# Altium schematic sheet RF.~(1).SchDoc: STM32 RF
size A4; Date: Not used; ApprovedBy: Not used; CheckedBy: Not used; Author: Not used; CompanyName: STMicroelectronics; DrawnBy: Not used; Engineer: Not used; Organization: Not used; Address1: Not used; Address2: Not used; Address3: Not used; Address4: Not used; DocumentNumber: Not used; Revision: Not used; SheetNumber: 5; SheetTotal: 5
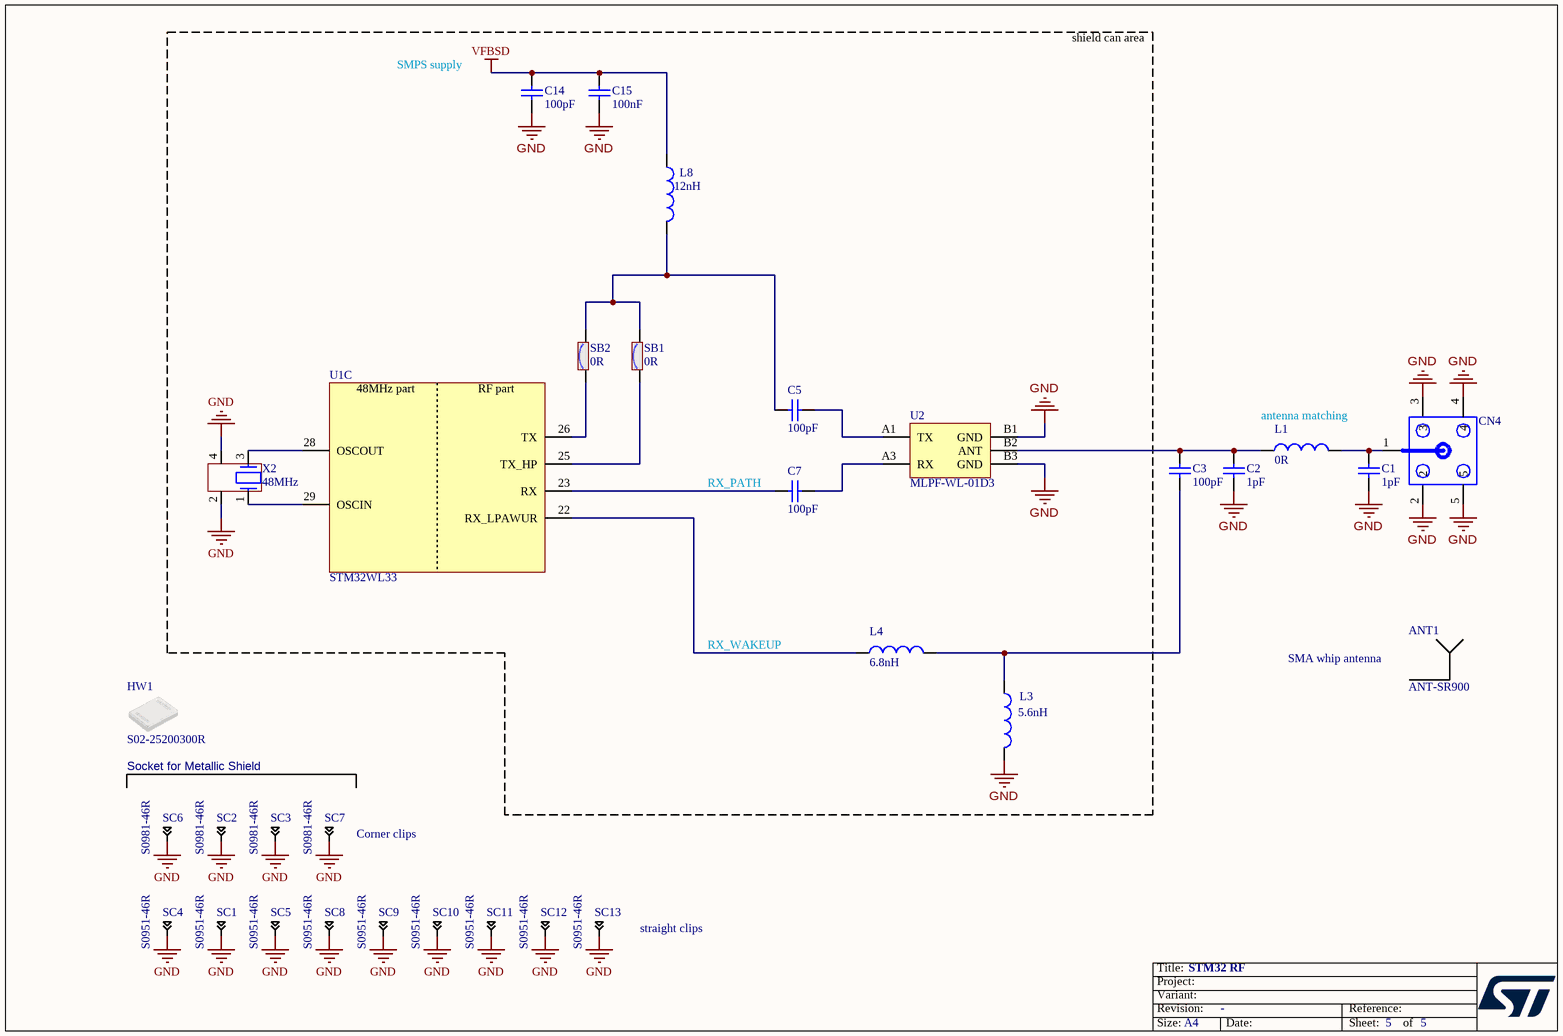
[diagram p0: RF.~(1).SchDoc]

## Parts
ANT1  value ANT-SR900  (hidden comment: ANT)  (mechanical)
C1  value 1pF  [C0402]  (hidden comment: Capacitor)
C2  value 1pF  [C0402]  (hidden comment: Capacitor)
C3  value 100pF  [C0402]  (hidden comment: Capacitor)
C5  value 100pF  [C0402]  (hidden comment: Capacitor)
C7  value 100pF  [C0402]  (hidden comment: Capacitor)
C14  value 100pF  [C0402]  (hidden comment: Capacitor)
C15  value 100nF  [C0402]  (hidden comment: Capacitor)
CN4  mmcx  [CON_SMA-RF_CINCH_142-0701-851]  (value not drawn)
HW1  value S02-25200300R  [SHIELD_HARWIN_S02-25200300_20X25_H3]  (hidden comment: S02-20150300)
L1  value 0R  [L0402]  (hidden comment: Inductor)
L3  value 5.6nH  [IND_0402_MURATA_LQG15HSXXXX02_H0P5]  (hidden comment: Inductor)
L4  value 6.8nH  [IND_0402_MURATA_LQG15HSXXXX02_H0P5]  (hidden comment: Inductor)
L8  value 12nH  [IND_0402_MURATA_LQW15ANXXXX00_H0P5]  (hidden comment: Inductor)
SB1  value 0R  [SOLDER-BRIDGE_R0201_0R]  (hidden comment: SB_ON)
SB2  value 0R  [SOLDER-BRIDGE_R0201_0R]  (hidden comment: SB_ON)
SC1  value S0951-46R  [CLIP_HARWIN_S0951-46R]  (hidden comment: Shield-clip_S0951-46R)
SC2  value S0981-46R  [CLIP_HARWIN_S0981-46R]  (hidden comment: Shield-clip_S0951-46R)
SC3  value S0981-46R  [CLIP_HARWIN_S0981-46R]  (hidden comment: Shield-clip_S0951-46R)
SC4  value S0951-46R  [CLIP_HARWIN_S0951-46R]  (hidden comment: Shield-clip_S0951-46R)
SC5  value S0951-46R  [CLIP_HARWIN_S0951-46R]  (hidden comment: Shield-clip_S0951-46R)
SC6  value S0981-46R  [CLIP_HARWIN_S0981-46R]  (hidden comment: Shield-clip_S0951-46R)
SC7  value S0981-46R  [CLIP_HARWIN_S0981-46R]  (hidden comment: Shield-clip_S0951-46R)
SC8  value S0951-46R  [CLIP_HARWIN_S0951-46R]  (hidden comment: Shield-clip_S0951-46R)
SC9  value S0951-46R  [CLIP_HARWIN_S0951-46R]  (hidden comment: Shield-clip_S0951-46R)
SC10  value S0951-46R  [CLIP_HARWIN_S0951-46R]  (hidden comment: Shield-clip_S0951-46R)
SC11  value S0951-46R  [CLIP_HARWIN_S0951-46R]  (hidden comment: Shield-clip_S0951-46R)
SC12  value S0951-46R  [CLIP_HARWIN_S0951-46R]  (hidden comment: Shield-clip_S0951-46R)
SC13  value S0951-46R  [CLIP_HARWIN_S0951-46R]  (hidden comment: Shield-clip_S0951-46R)
U1  STM32WL33  [ICC_QFN48-EPAD-4P5X4P5_6X6_P040]  (part C of 3)
U2  value MLPF-WL-01D3  [ICC_CSPG5_1P5X1P9_P060]  (hidden comment: MLPF-WL-0xD3)
X2  value 48MHz  [CRY_NX1612SA_4P]  (hidden comment: XTAL_4_PINS)

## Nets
GND: C1.1 C2.1 C14.2 C15.1 CN4.2 CN4.3 CN4.4 CN4.5 L3.2 SC1.1 SC2.1 SC3.1 SC4.1 SC5.1 SC6.1 SC7.1 SC8.1 SC9.1 SC10.1 SC11.1 SC12.1 SC13.1 U2.B1(GND) U2.B3(GND) X2.2 X2.4
VFBSD: C14.1 C15.2 L8.1
NetC1_2: C1.2 CN4.1 L1.2
NetC2_2: C2.2 C3.2 L1.1 U2.B2(ANT)
NetC3_1: C3.1 L3.1 L4.2
NetC5_1: C5.1 U2.A1(TX)
NetC5_2: C5.2 L8.2 SB1.2 SB2.2
NetC7_1: C7.1 U1.23(RX)
NetC7_2: C7.2 U2.A3(RX)
NetL4_1: L4.1 U1.22(RX_LPAWUR)
NetSB1_1: SB1.1 U1.25(TX_HP)
NetSB2_1: SB2.1 U1.26(TX)
NetU1_28: U1.28(OSCOUT) X2.3
NetU1_29: U1.29(OSCIN) X2.1

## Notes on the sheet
- shield can area
- SMPS supply
- antenna matching
- (near C7) RX_PATH
- RX_WAKEUP
- SMA whip antenna
- Socket for Metallic Shield
- (near SC7) Corner clips
- (near SC13) straight clips

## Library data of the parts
ANT1 = MCD-03598: Antenna, 868MHz To 915MHz, Compressed whip, SMA right angle; Part_Type: Misc; Part_Preference: Recommended; Manufacturer: LPRS; Component_Country_Of_Origin: China°; ShowFields: YES; ID: 5714
C1 C2 = MCD-01600: Capacitor, MLCC, 1pF, 50V, NPO, +/-0.1pF, 0402, T=0.5mm; Part_Preference: Recommended; Manufacturer: YAGEO; Manufacturer_Part_Number: CC0402BRNPO9BN1R0; Component_Country_Of_Origin: China; ShowFields: YES; ID: 3700
C3 C7 = MCD-03446: Capacitor, MLCC, 100pF, 50V, COG, +/-1%, 0402, T=0.5mm; Part_Preference: Recommended; Manufacturer: MURATA; Manufacturer_Part_Number: GCM1555C1H101FA16; Order_Code_RS: 247-7780; Component_Country_Of_Origin: China,  Japan, Philippines, Singapore; ShowFields: YES; ID: 5562
C5 C14 = MCD-03446: Capacitor, MLCC, 100pF, 50V, COG, 1%, 0402, T=0.5mm; Part_Preference: Recommended; Manufacturer: MURATA; Manufacturer_Part_Number: GCM1555C1H101FA16; Order_Code_RS: 247-7780; ShowFields: YES; ID: 5562
C15 = MCD-03442: Capacitor, MLCC, 100nF, ±10%, X7R, 25V, 0402, T=0.5mm; Part_Preference: Recommended; Manufacturer: MURATA; Manufacturer_Part_Number: GRM155R71E104KE14D; Order_Code_RS: 247-8011; ShowFields: YES; ID: 5558
CN4 = MCD-02072: Jack_SMA, VR, PCB edge, 50R, T=7.92mm; Part_Type: Connector; Part_Preference: Recommended; Manufacturer: CINCH; Manufacturer_Part_Number: 142-0701-851; Order_Code_RS: 885-7532; Component_Country_Of_Origin: United States; ShowFields: YES; ID: 4172
HW1 = MCD-03503: RFI shield CAN, 25x20x3mm; Part_Type: Misc; Part_Preference: Recommended; Manufacturer: HARWIN; Order_Code_RS: 247-9196; Component_Country_Of_Origin: UK°; ShowFields: YES; ID: 5619
L1 = MCD-01937: Resistor, 0R, 0402, +/-5%, 1/16W; Part_Preference: Recommended; Manufacturer: YAGEO; Manufacturer_Part_Number: RC0402JR-070RL; Order_Code_RS: 618-5804; Component_Country_Of_Origin: China; ShowFields: YES; ID: 4037
L3 = MCD-03462: Inductor, 5.6nH, +/-0.3nH, 0.65A, 180mR, 0402, T=0.5mm; Part_Preference: Recommended; Manufacturer: MURATA; Manufacturer_Part_Number: LQG15HS5N6S02; Order_Code_RS: 2840123RL; ShowFields: YES; ID: 5578; Component_Country_Of_Origin: Japan
L4 = MCD-03461: Inductor, 6.8nH, +/-3%, 0.6A, 220mR, 0402, T=0.5mm; Manufacturer: MURATA; Manufacturer_Part_Number: LQG15HS6N8H02; Part_Preference: Recommended; Order_Code_RS: 3354298; Component_Country_Of_Origin: Japan; ShowFields: YES; ID: 5577
L8 = MCD-03456: Inductor, 12nH, +/-2%, 500mA, 0R14, 0402, T=0.5mm; Part_Preference: Recommended; Manufacturer: MURATA; Manufacturer_Part_Number: LQW15AN12NG00D; Order_Code_RS: 2840126RL; ShowFields: YES; ID: 5572; Component_Country_Of_Origin: Japan, Malaysia
SB1 SB2 = MCD-03219: Resistor, 0R, 0201, Solder Bridge ON , 1/20W,; Part_Type: Misc; Part_Preference: Recommended; Manufacturer: YAGEO; Manufacturer_Part_Number: RC0201JR-070RL; Order_Code_RS: 198-7623; Component_Country_Of_Origin: China; ShowFields: YES; ID: 5335
SC1 SC4 SC5 SC8 = MCD-01587: shield clip Harwin S0951-46R to fix RF shielded cavity; Part_Type: Misc; Part_Preference: Recommended; Component_Country_Of_Origin: South Korea
SC2 SC3 SC6 SC7 = MCD-02164: shield clip Harwin S0981-46R to fix RF shielded cavity - SMT RFI Shield Clip, Corner (T+R); Part_Type: Misc; Part_Preference: Recommended; Order_Code_RS: 161-3702; Component_Country_Of_Origin: South Korea; ShowFields: YES; ID: 4264
SC9-SC13 = MCD-01587: RFI shield clip mini TIN SMD; Part_Type: Mechanical; Part_Preference: Recommended; Manufacturer: HARWIN; Component_Country_Of_Origin: South Korea; ShowFields: YES; ID: 3687
U1 = MCD-03488: IC, Programmable Sub-1GHz wireless SoC; Part_Preference: Recommended; Manufacturer: STMICROELECTRONICS; Component_Country_Of_Origin: Unknown; ShowFields: YES; ID: 5604
U2 = MCD-03962: IC, 862 To 928MHz,16dBm, 4L PCB, IPD for STM32WL3; Part_Preference: Not recommended; Manufacturer: STMICROELECTRONICS; ShowFields: YES; ID: 6078; Component_Country_Of_Origin: Unknown
X2 = MCD-03559: Crystal, 48MHz, 8pF, +/-10 ppm, 22R, 1.6x1.2mm; Part_Type: Crystal_Osc; Part_Preference: Recommended; Manufacturer: NDK; Manufacturer_Part_Number: NX1612SA-48.000 MHz-EXS00A-CS12140; ShowFields: YES; ID: 5675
